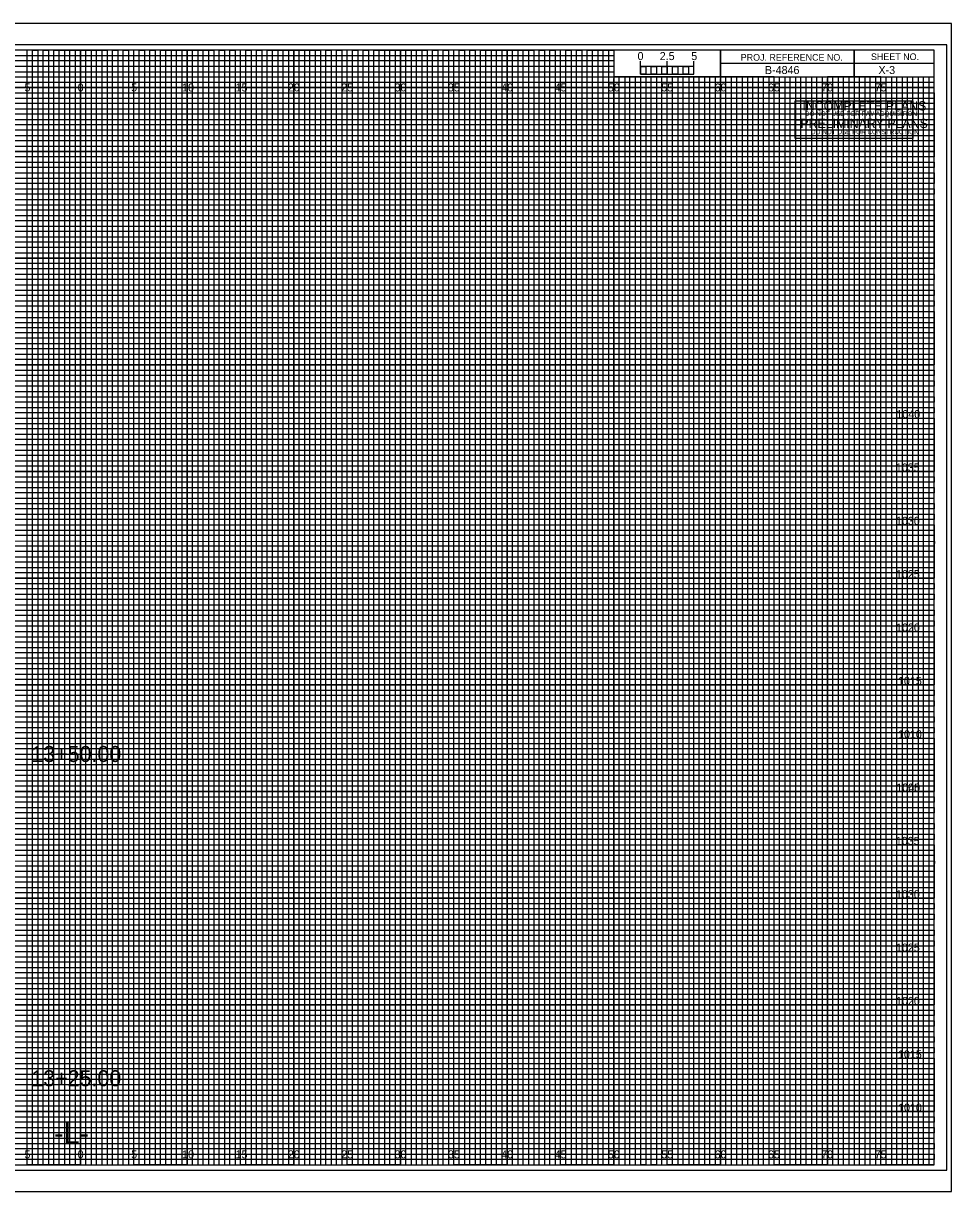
# Model space of a CAD drawing. Extents: x -7 to 162, y -2 to 987.
# Drawn here: x 74.6 to 161.7, y 217.5 to 327 of the extents above; entities that cross this region are included whole.
import ezdxf

# ---------------------------------------------------------------- set-up
doc = ezdxf.new("R2010")
doc.units = 0
for name, color, linetype in [('Default', 7, 'Continuous'), ('Exist Cross Section Cell', 7, 'Continuous'), ('Exist XS Center Line Elevation Label', 7, 'Continuous'), ('Exist XS Ground Line', 7, 'Continuous'), ('Prop CMT Concrete Structures', 7, 'Continuous'), ('Prop CMT DNC', 7, 'Continuous'), ('Prop CMT Guardrail Graphics', 7, 'Continuous'), ('Prop CMT Guardrail Widen Shoulder', 7, 'Continuous'), ('Prop CMT Pvmt Course 1', 7, 'Continuous'), ('Prop CMT Pvmt Surface', 7, 'Continuous'), ('Prop CMT Pvmt Surface Shoulder', 7, 'Continuous'), ('Prop CMT Shld Paved Course 1', 7, 'Continuous'), ('Prop CMT Shoulder Point', 7, 'Continuous'), ('Prop CMT Slope Grass', 7, 'Continuous'), ('Prop CMT Subgrade Earthwork', 7, 'Continuous'), ('Prop XS SE Text', 7, 'Continuous'), ('Prop XS Side Slope Text', 7, 'Continuous'), ('Typical Text Label CELL', 7, 'Continuous')]:
    doc.layers.add(name, color=color, linetype=linetype)

msp = doc.modelspace()

# ---------------------------------------------------------------- linework, layer by layer
at = {"layer": 'Default'}
for points in [[(146.99, 317.97), (146.99, 319.73), (158.01, 319.73), (158.01, 317.97)], [(146.99, 316.2), (146.99, 317.97), (158.01, 317.97), (158.01, 316.2)]]:
    msp.add_lwpolyline(points, close=True, dxfattribs=at)
at = {"layer": 'Exist XS Center Line Elevation Label'}
for points in [[(72.5, 220), (77.5, 220), (77.5, 324.5), (82.5, 324.5), (82.5, 220), (87.5, 220), (87.5, 324.5), (92.5, 324.5), (92.5, 220), (97.5, 220), (97.5, 324.5), (102.5, 324.5), (102.5, 220), (107.5, 220), (107.5, 324.5), (112.5, 324.5), (112.5, 220), (117.5, 220), (117.5, 324.5), (122.5, 324.5), (122.5, 220), (127.5, 220), (127.5, 324.5), (129.97, 324.5), (130, 324.5), (130, 322), (132.5, 322), (132.5, 220), (137.5, 220), (137.5, 322), (142.5, 322), (142.5, 220), (147.5, 220), (147.5, 322), (152.5, 322), (152.5, 220), (157.5, 220), (157.5, 322)], [(0, 322), (137.5, 322)], [(0, 312.5), (160, 312.5), (160, 317.5), (0, 317.5)], [(0, 302.5), (160, 302.5), (160, 307.5), (0, 307.5)], [(0, 292.5), (160, 292.5), (160, 297.5), (0, 297.5)], [(0, 282.5), (160, 282.5), (160, 287.5), (0, 287.5)], [(0, 272.5), (160, 272.5), (160, 277.5), (0, 277.5)], [(0, 262.5), (160, 262.5), (160, 267.5), (0, 267.5)], [(0, 252.5), (160, 252.5), (160, 257.5), (0, 257.5)], [(0, 242.5), (160, 242.5), (160, 247.5), (0, 247.5)], [(0, 232.5), (160, 232.5), (160, 237.5), (0, 237.5)], [(0, 222.5), (160, 222.5), (160, 227.5), (0, 227.5)]]:
    msp.add_lwpolyline(points, dxfattribs=at)
at = {"layer": 'Exist XS Ground Line'}
for p, q in [((75, 324.5), (70, 324.5)), ((75, 220), (75, 324.5)), ((85, 324.5), (80, 324.5)), ((80, 324.5), (80, 220)), ((85, 220), (85, 324.5)), ((95, 324.5), (90, 324.5)), ((90, 324.5), (90, 220)), ((95, 220), (95, 324.5)), ((105, 324.5), (100, 324.5)), ((100, 324.5), (100, 220)), ((105, 220), (105, 324.5)), ((115, 324.5), (110, 324.5)), ((110, 324.5), (110, 220)), ((115, 220), (115, 324.5)), ((125, 324.5), (120, 324.5)), ((120, 324.5), (120, 220)), ((125, 220), (125, 324.5)), ((130, 324.5), (130, 220)), ((135, 220), (135, 322)), ((145, 322), (140, 322)), ((140, 322), (140, 220)), ((145, 220), (145, 322)), ((155, 322), (150, 322)), ((150, 322), (150, 220)), ((155, 220), (155, 322)), ((80, 220), (75, 220)), ((90, 220), (85, 220)), ((100, 220), (95, 220)), ((110, 220), (105, 220)), ((120, 220), (115, 220)), ((130, 220), (125, 220)), ((140, 220), (135, 220)), ((150, 220), (145, 220)), ((160, 220), (155, 220)), ((160, 220), (160, 220))]:
    msp.add_line(p, q, dxfattribs=at)
for points in [[(0, 320), (160, 320), (160, 315), (0, 315)], [(0, 310), (160, 310), (160, 305), (0, 305)], [(0, 300), (160, 300), (160, 295), (0, 295)], [(0, 290), (160, 290), (160, 285), (0, 285)], [(0, 280), (160, 280), (160, 275), (0, 275)], [(0, 270), (160, 270), (160, 265), (0, 265)], [(0, 260), (160, 260), (160, 255), (0, 255)], [(0, 250), (160, 250), (160, 245), (0, 245)], [(0, 240), (160, 240), (160, 235), (0, 235)], [(0, 230), (160, 230), (160, 225), (0, 225)]]:
    msp.add_lwpolyline(points, dxfattribs=at)
at = {"layer": 'Prop CMT Concrete Structures'}
for p, q in [((75, 220), (75, 324.5)), ((80, 220), (80, 324.5)), ((85, 220), (85, 324.5)), ((90, 220), (90, 324.5)), ((95, 220), (95, 324.5)), ((100, 220), (100, 324.5)), ((105, 220), (105, 324.5)), ((110, 220), (110, 324.5)), ((115, 220), (115, 324.5)), ((120, 220), (120, 324.5)), ((125, 220), (125, 324.5)), ((130, 220), (130, 321.84)), ((135, 220), (135, 321.84)), ((140, 220), (140, 321.84)), ((145, 220), (145, 321.84)), ((150, 220), (150, 321.84)), ((155, 220), (155, 321.84)), ((0, 320), (160, 320)), ((0, 315), (160, 315)), ((0, 310), (160, 310)), ((0, 305), (160, 305)), ((0, 300), (160, 300)), ((0, 295), (160, 295)), ((0, 290), (160, 290)), ((0, 285), (160, 285)), ((0, 280), (160, 280)), ((0, 275), (160, 275)), ((0, 270), (160, 270)), ((0, 265), (160, 265)), ((0, 260), (160, 260)), ((0, 255), (160, 255)), ((0, 250), (160, 250)), ((0, 245), (160, 245)), ((0, 240), (160, 240)), ((0, 235), (160, 235)), ((0, 230), (160, 230)), ((0, 225), (160, 225))]:
    msp.add_line(p, q, dxfattribs=at)
at = {"layer": 'Prop CMT Guardrail Widen Shoulder'}
for p, q in [((161.65, 327), (-6.7, 327)), ((-6.7, 217.5), (161.65, 217.5))]:
    msp.add_line(p, q, dxfattribs=at)
at = {"layer": 'Prop CMT Pvmt Course 1'}
msp.add_lwpolyline([(-6.7, 217.5), (161.65, 217.5), (161.65, 327), (-6.7, 327)], close=True, dxfattribs=at)
at = {"layer": 'Prop CMT Pvmt Surface'}
for p, q in [((133.5, 322), (133, 322)), ((133, 322), (133, 220)), ((133.5, 220), (133.5, 322)), ((134.5, 322), (134, 322)), ((134, 322), (134, 220)), ((134.5, 220), (134.5, 322)), ((133, 220), (132.5, 220)), ((134, 220), (133.5, 220))]:
    msp.add_line(p, q, dxfattribs=at)
for points in [[(75, 220), (75.5, 220), (75.5, 324.5), (76, 324.5), (76, 220)], [(76, 220), (76.5, 220), (76.5, 324.5), (77, 324.5), (77, 220)], [(77.5, 220), (78, 220), (78, 324.5), (78.5, 324.5), (78.5, 220)], [(78.5, 220), (79, 220), (79, 324.5), (79.5, 324.5), (79.5, 220)], [(80, 220), (80.5, 220), (80.5, 324.5), (81, 324.5), (81, 220)], [(81, 220), (81.5, 220), (81.5, 324.5), (82, 324.5), (82, 220)], [(82.5, 220), (83, 220), (83, 324.5), (83.5, 324.5), (83.5, 220)], [(83.5, 220), (84, 220), (84, 324.5), (84.5, 324.5), (84.5, 220)], [(85, 220), (85.5, 220), (85.5, 324.5), (86, 324.5), (86, 220)], [(86, 220), (86.5, 220), (86.5, 324.5), (87, 324.5), (87, 220)], [(87.5, 220), (88, 220), (88, 324.5), (88.5, 324.5), (88.5, 220)], [(88.5, 220), (89, 220), (89, 324.5), (89.5, 324.5), (89.5, 220)], [(90, 220), (90.5, 220), (90.5, 324.5), (91, 324.5), (91, 220)], [(91, 220), (91.5, 220), (91.5, 324.5), (92, 324.5), (92, 220)], [(92.5, 220), (93, 220), (93, 324.5), (93.5, 324.5), (93.5, 220)], [(93.5, 220), (94, 220), (94, 324.5), (94.5, 324.5), (94.5, 220)], [(95, 220), (95.5, 220), (95.5, 324.5), (96, 324.5), (96, 220)], [(96, 220), (96.5, 220), (96.5, 324.5), (97, 324.5), (97, 220)], [(97.5, 220), (98, 220), (98, 324.5), (98.5, 324.5), (98.5, 220)], [(98.5, 220), (99, 220), (99, 324.5), (99.5, 324.5), (99.5, 220)], [(100, 220), (100.5, 220), (100.5, 324.5), (101, 324.5), (101, 220)], [(101, 220), (101.5, 220), (101.5, 324.5), (102, 324.5), (102, 220)], [(102.5, 220), (103, 220), (103, 324.5), (103.5, 324.5), (103.5, 220)], [(103.5, 220), (104, 220), (104, 324.5), (104.5, 324.5), (104.5, 220)], [(105, 220), (105.5, 220), (105.5, 324.5), (106, 324.5), (106, 220)], [(106, 220), (106.5, 220), (106.5, 324.5), (107, 324.5), (107, 220)], [(107.5, 220), (108, 220), (108, 324.5), (108.5, 324.5), (108.5, 220)], [(108.5, 220), (109, 220), (109, 324.5), (109.5, 324.5), (109.5, 220)], [(110, 220), (110.5, 220), (110.5, 324.5), (111, 324.5), (111, 220)], [(111, 220), (111.5, 220), (111.5, 324.5), (112, 324.5), (112, 220)], [(112.5, 220), (113, 220), (113, 324.5), (113.5, 324.5), (113.5, 220)], [(113.5, 220), (114, 220), (114, 324.5), (114.5, 324.5), (114.5, 220)], [(115, 220), (115.5, 220), (115.5, 324.5), (116, 324.5), (116, 220)], [(116, 220), (116.5, 220), (116.5, 324.5), (117, 324.5), (117, 220)], [(117.5, 220), (118, 220), (118, 324.5), (118.5, 324.5), (118.5, 220)], [(118.5, 220), (119, 220), (119, 324.5), (119.5, 324.5), (119.5, 220)], [(120, 220), (120.5, 220), (120.5, 324.5), (121, 324.5), (121, 220)], [(121, 220), (121.5, 220), (121.5, 324.5), (122, 324.5), (122, 220)], [(122.5, 220), (123, 220), (123, 324.5), (123.5, 324.5), (123.5, 220)], [(123.5, 220), (124, 220), (124, 324.5), (124.5, 324.5), (124.5, 220)], [(125, 220), (125.5, 220), (125.5, 324.5), (126, 324.5), (126, 220)], [(126, 220), (126.5, 220), (126.5, 324.5), (127, 324.5), (127, 220)], [(127.5, 220), (128, 220), (128, 324.5), (128.5, 324.5), (128.5, 220)], [(128.5, 220), (129, 220), (129, 324.5), (129.5, 324.5), (129.5, 220)], [(130, 220), (130.5, 220), (130.5, 322), (131.01, 322), (131.01, 220)], [(131, 220), (131.5, 220), (131.5, 322), (132, 322), (132, 220)], [(135, 220), (135.49, 220), (135.49, 322), (136, 322), (136, 220)], [(136, 220), (136.5, 220), (136.5, 322), (137.03, 322), (137.03, 220)], [(137.5, 220), (138, 220), (138, 322), (138.5, 322), (138.5, 220)], [(138.5, 220), (139, 220), (139, 322), (139.5, 322), (139.5, 220)], [(140, 220), (140.5, 220), (140.5, 322), (141, 322), (141, 220)], [(141, 220), (141.5, 220), (141.5, 322), (142, 322), (142, 220)], [(142.5, 220), (143, 220), (143, 322), (143.5, 322), (143.5, 220)], [(143.5, 220), (144, 220), (144, 322), (144.5, 322), (144.5, 220)], [(145, 220), (145.5, 220), (145.5, 322), (146, 322), (146, 220)], [(146, 220), (146.5, 220), (146.5, 322), (147, 322), (147, 220)], [(147.5, 220), (148, 220), (148, 322), (148.5, 322), (148.5, 220)], [(148.5, 220), (149, 220), (149, 322), (149.5, 322), (149.5, 220)], [(150, 220), (150.5, 220), (150.5, 322), (151, 322), (151, 220)], [(151, 220), (151.5, 220), (151.5, 322), (152, 322), (152, 220)], [(152.5, 220), (153, 220), (153, 322), (153.5, 322), (153.5, 220)], [(153.5, 220), (154, 220), (154, 322), (154.5, 322), (154.5, 220)], [(155, 220), (155.5, 220), (155.5, 322), (156, 322), (156, 220)], [(156, 220), (156.5, 220), (156.5, 322), (157, 322), (157, 220)], [(157.5, 220), (158, 220), (158, 322), (158.5, 322), (158.5, 220)], [(158.5, 220), (159, 220), (159, 322), (159.5, 322), (159.5, 220)]]:
    msp.add_lwpolyline(points, dxfattribs=at)
at = {"layer": 'Prop CMT Pvmt Surface Shoulder'}
for p, q in [((132.5, 322.25), (132.5, 323.45)), ((132.5, 322.95), (132.5, 323.45)), ((135, 322.25), (135, 323.45)), ((137.5, 322.25), (137.5, 323.45)), ((137.5, 322.95), (137.5, 323.45))]:
    msp.add_line(p, q, dxfattribs=at)
for points in [[(137.5, 322.95), (132.5, 322.95), (132.5, 322.25), (137.5, 322.25)], [(132.5, 322.95), (133, 322.95), (133, 322.25), (132.5, 322.25)], [(133.5, 322.95), (134, 322.95), (134, 322.25), (133.5, 322.25)], [(134.5, 322.95), (135, 322.95), (135, 322.25), (134.5, 322.25)], [(135.5, 322.95), (136, 322.95), (136, 322.25), (135.5, 322.25)], [(136.5, 322.95), (137, 322.95), (137, 322.25), (136.5, 322.25)]]:
    msp.add_lwpolyline(points, close=True, dxfattribs=at)
at = {"layer": 'Prop CMT Shld Paved Course 1'}
for p, q in [((0, 324), (130, 324)), ((130, 323.49), (0, 323.49)), ((130, 324), (130, 323.49)), ((0, 323), (130, 323)), ((130, 322.44), (0, 322.44)), ((130, 323), (130, 322.44)), ((0, 321.5), (160, 321.5))]:
    msp.add_line(p, q, dxfattribs=at)
for points in [[(0, 321), (135, 321), (160, 321), (160, 321), (0, 321)], [(0, 320.5), (160, 320.5), (160, 319.5), (0, 319.5)], [(0, 319), (160, 319), (160, 318.5), (0, 318.49)], [(0, 318), (160, 318), (160, 317), (0, 317)], [(0, 316.5), (160, 316.5), (160, 316), (0, 316)], [(0, 315.5), (160, 315.5), (160, 314.5), (0, 314.5)], [(0, 314), (160, 314), (160, 313.5), (0, 313.5)], [(0, 313), (160, 313), (160, 312), (0, 312)], [(0, 311.5), (160, 311.5), (160, 311), (0, 311)], [(0, 310.5), (160, 310.5), (160, 309.5), (0, 309.5)], [(0, 309), (160, 309), (160, 308.5), (0, 308.5)], [(0, 308), (160, 308), (160, 306.98), (160, 306.5), (160, 306), (0, 306)], [(0, 307), (160, 307), (160, 306.5), (0, 306.5)], [(0, 305.5), (160, 305.5), (160, 304.5), (0, 304.51)], [(0, 304.51), (160, 304.5), (160, 304), (0, 304)], [(0, 303.5), (160, 303.5), (160, 303), (0, 303)], [(0, 302), (160, 302), (160, 301.5), (0, 301.5)], [(0, 301), (160, 301), (160, 300.5), (0, 300.5)], [(-0.04, 299.44), (160, 299.44), (160, 298.94), (-0.04, 298.94)], [(0, 298.5), (160, 298.5), (160, 298), (0, 298)], [(0, 297), (160, 297), (160, 296.5), (0, 296.5)], [(0, 296), (160, 296), (160, 295.5), (0, 295.5)], [(0, 294.5), (160, 294.5), (160, 294), (0, 294)], [(0, 293.5), (160, 293.5), (160, 293), (0, 293)], [(0, 292), (160, 292), (160, 291.5), (0, 291.5)], [(0, 291), (160, 291), (160, 290.5), (0, 290.5)], [(0, 289.5), (160, 289.5), (160, 288.99), (0, 289)], [(0, 288.5), (160, 288.5), (160, 288), (0, 288)], [(0, 287), (160, 287), (160, 286.5), (0, 286.5)], [(0, 286), (160, 286), (160, 285.5), (0, 285.5)], [(0, 284.5), (160, 284.5), (160, 284), (0, 284)], [(0, 283.5), (160, 283.5), (160, 283), (0, 283)], [(0, 282), (160, 282), (160, 281.5), (0, 281.5)], [(0, 281), (160, 281), (160, 280.5), (0, 280.5)], [(0, 279.5), (160, 279.5), (160, 279), (0, 279)], [(0, 278.5), (160.03, 278.45), (160, 278), (0, 278)], [(0, 277), (160, 277), (160, 276.5), (0, 276.5)], [(0, 276), (160, 276), (160, 275.5), (0, 275.5)], [(0, 274.5), (160, 274.5), (160, 274), (0, 274)], [(0, 273.5), (160, 273.5), (160, 273), (0, 273)], [(0, 272), (160, 272), (160, 271.5), (0, 271.5)], [(0, 271), (160, 271), (160, 270.5), (0, 270.5)], [(0, 269.5), (160, 269.5), (160, 269), (0, 269)], [(0, 268.5), (160, 268.5), (160, 268), (0, 268)], [(0, 267), (160, 267), (160, 266.5), (0, 266.5)], [(0, 266), (160, 266), (160, 265.5), (0, 265.5)], [(0, 264.5), (160, 264.5), (160, 264), (0, 264)], [(0, 263.5), (160, 263.5), (160, 263), (0, 263)], [(0, 262), (160, 262), (160, 261.5), (0, 261.5)], [(0, 261), (160, 261), (160, 260.5), (0, 260.5)], [(0, 259.5), (160, 259.5), (160, 258.99), (0, 259)], [(0, 258.5), (160, 258.5), (160, 258), (0, 258)], [(0, 257), (160, 257), (160, 256.5), (0, 256.5)], [(0, 256), (160, 256), (160, 255.5), (0, 255.5)], [(0, 254.5), (160, 254.5), (160, 254), (0, 254)], [(0, 253.5), (160, 253.5), (160, 253), (0, 253)], [(0, 252), (160, 252), (160, 251.5), (0, 251.5)], [(0, 251), (160, 251), (160, 250.5), (0, 250.5)], [(0, 249.5), (160, 249.5), (160, 249), (0, 249)], [(0, 248.5), (160.03, 248.46), (160, 248), (0, 248)], [(0, 247), (160, 247), (160, 246.5), (0, 246.5)], [(0, 246), (160, 246), (160, 245.5), (0, 245.5)], [(0, 244.5), (160, 244.5), (160, 244), (0, 244)], [(0, 243.5), (160, 243.5), (160, 243), (0, 243)], [(0, 242), (160, 242), (160, 241.5), (0, 241.5)], [(0, 241), (160, 241), (160, 240.5), (0, 240.5)], [(0, 239.5), (160, 239.5), (160, 239), (0, 239)], [(0, 238.5), (160, 238.5), (160, 238), (0, 238)], [(0, 237), (160, 237), (160, 236.5), (0, 236.5)], [(0, 236), (160, 236), (160, 235.5), (0, 235.5)], [(0, 234.5), (160, 234.5), (160, 234), (0, 234)], [(0, 233.5), (160, 233.5), (160, 233), (0, 233)], [(0, 232), (160, 232), (160, 231.5), (0, 231.5)], [(0, 231), (160, 231), (160, 230.5), (0, 230.5)], [(0, 229.5), (160, 229.5), (160, 229), (0, 229)], [(0, 228.5), (160, 228.5), (160, 228), (0, 228)], [(0, 227), (160, 227), (160, 226.5), (0, 226.5)], [(0, 226), (160, 226), (160, 225.5), (0, 225.5)], [(0, 224.5), (160, 224.5), (160, 224), (0, 224)], [(0, 223.5), (160, 223.5), (160, 223), (0, 223)], [(0, 222), (160, 222), (160, 221.5), (0, 221.5)], [(0, 221), (160, 221), (160, 220.5), (0, 220.5)]]:
    msp.add_lwpolyline(points, dxfattribs=at)
at = {"layer": 'Prop CMT Slope Grass'}
msp.add_lwpolyline([(-5.4, 219.5), (161.2, 219.5), (161.2, 325), (-5.4, 325)], close=True, dxfattribs=at)
at = {"layer": 'Prop CMT Subgrade Earthwork'}
for p, q in [((152.5, 324.5), (152.5, 322)), ((152.5, 322), (152.5, 324.5)), ((160, 323.25), (140, 323.25)), ((140, 323.25), (140, 322)), ((140, 322), (160, 322))]:
    msp.add_line(p, q, dxfattribs=at)
for points in [[(160, 324.5), (0, 324.5), (0, 220), (160, 220)], [(140, 324.5), (130, 324.5), (130, 322.01), (140, 322.01)], [(160, 324.5), (140, 324.5), (140, 322), (160, 322)]]:
    msp.add_lwpolyline(points, close=True, dxfattribs=at)

# ---------------------------------------------------------------- texts
at = {"layer": 'Default'}
for s, height, p in [('INCOMPLETE PLANS', 0.864, (147.66, 318.84)), ('DO NOT USE FOR R/W ACQUISITION', 0.432, (147.9, 318.32)), ('PRELIMINARY PLANS', 0.864, (147.47, 317.19)), ('DO NOT USE FOR CONSTRUCTION', 0.432, (148.46, 316.61))]:
    msp.add_text(s, height=height, dxfattribs=at).set_placement(p)
at = {"layer": 'Exist Cross Section Cell'}
for s, p in [('5', (74.74, 320.62)), ('0', (79.73, 320.62)), ('0', (79.73, 320.62)), ('5', (84.74, 320.62)), ('10', (89.52, 320.62)), ('15', (94.53, 320.62)), ('20', (99.43, 320.62)), ('25', (104.44, 320.62)), ('30', (109.43, 320.62)), ('35', (114.44, 320.62)), ('40', (119.43, 320.62)), ('45', (124.44, 320.62)), ('50', (129.43, 320.62)), ('55', (134.44, 320.62)), ('60', (139.43, 320.62)), ('65', (144.44, 320.62)), ('70', (149.43, 320.62)), ('75', (154.44, 320.62)), ('5', (74.74, 220.62)), ('0', (79.73, 220.62)), ('0', (79.73, 220.62)), ('5', (84.74, 220.62)), ('10', (89.52, 220.62)), ('15', (94.53, 220.62)), ('20', (99.43, 220.62)), ('25', (104.44, 220.62)), ('30', (109.43, 220.62)), ('35', (114.44, 220.62)), ('40', (119.43, 220.62)), ('45', (124.44, 220.62)), ('50', (129.43, 220.62)), ('55', (134.44, 220.62)), ('60', (139.43, 220.62)), ('65', (144.44, 220.62)), ('70', (149.43, 220.62)), ('75', (154.44, 220.62))]:
    msp.add_text(s, height=0.75, dxfattribs=at).set_placement(p)
at = {"layer": 'Prop CMT DNC'}
msp.add_text('-L-', height=2, dxfattribs=at).set_placement((77.53, 222))
at = {"layer": 'Prop CMT Guardrail Graphics'}
msp.add_text('B-4846', height=0.75, dxfattribs=at).set_placement((144.15, 322.25))
at = {"layer": 'Prop CMT Pvmt Surface Shoulder'}
msp.add_text('0', height=0.75, dxfattribs=at).set_placement((132.21, 323.56))
at = {"layer": 'Prop CMT Shoulder Point'}
for s, p in [('2.5', (134.29, 323.56)), ('5', (137.24, 323.56))]:
    msp.add_text(s, height=0.75, dxfattribs=at).set_placement(p)
at = {"layer": 'Prop CMT Subgrade Earthwork'}
for s, p in [('PROJ. REFERENCE NO.', (141.88, 323.5)), ('SHEET NO.', (154.09, 323.56))]:
    msp.add_text(s, height=0.625, dxfattribs=at).set_placement(p)
at = {"layer": 'Prop XS SE Text'}
msp.add_text('X-3', height=0.75, dxfattribs=at).set_placement((154.79, 322.25))
at = {"layer": 'Prop XS Side Slope Text'}
for s, p in [('13+50.00', (75.39, 257.77)), ('13+25.00', (75.39, 227.38))]:
    msp.add_text(s, height=1.5, dxfattribs=at).set_placement(p)
at = {"layer": 'Typical Text Label CELL'}
for s, p in [('1040', (156.47, 290)), ('1035', (156.42, 285)), ('1030', (156.43, 280)), ('1025', (156.43, 275)), ('1020', (156.44, 270)), ('1015', (156.62, 265)), ('1010', (156.63, 260)), ('1005', (156.45, 255)), ('1040', (156.47, 255)), ('1035', (156.42, 250)), ('1030', (156.43, 245)), ('1025', (156.43, 240)), ('1020', (156.44, 235)), ('1015', (156.62, 230)), ('1010', (156.63, 225))]:
    msp.add_text(s, height=0.75, dxfattribs=at).set_placement(p)

doc.saveas('drawing.dxf')
